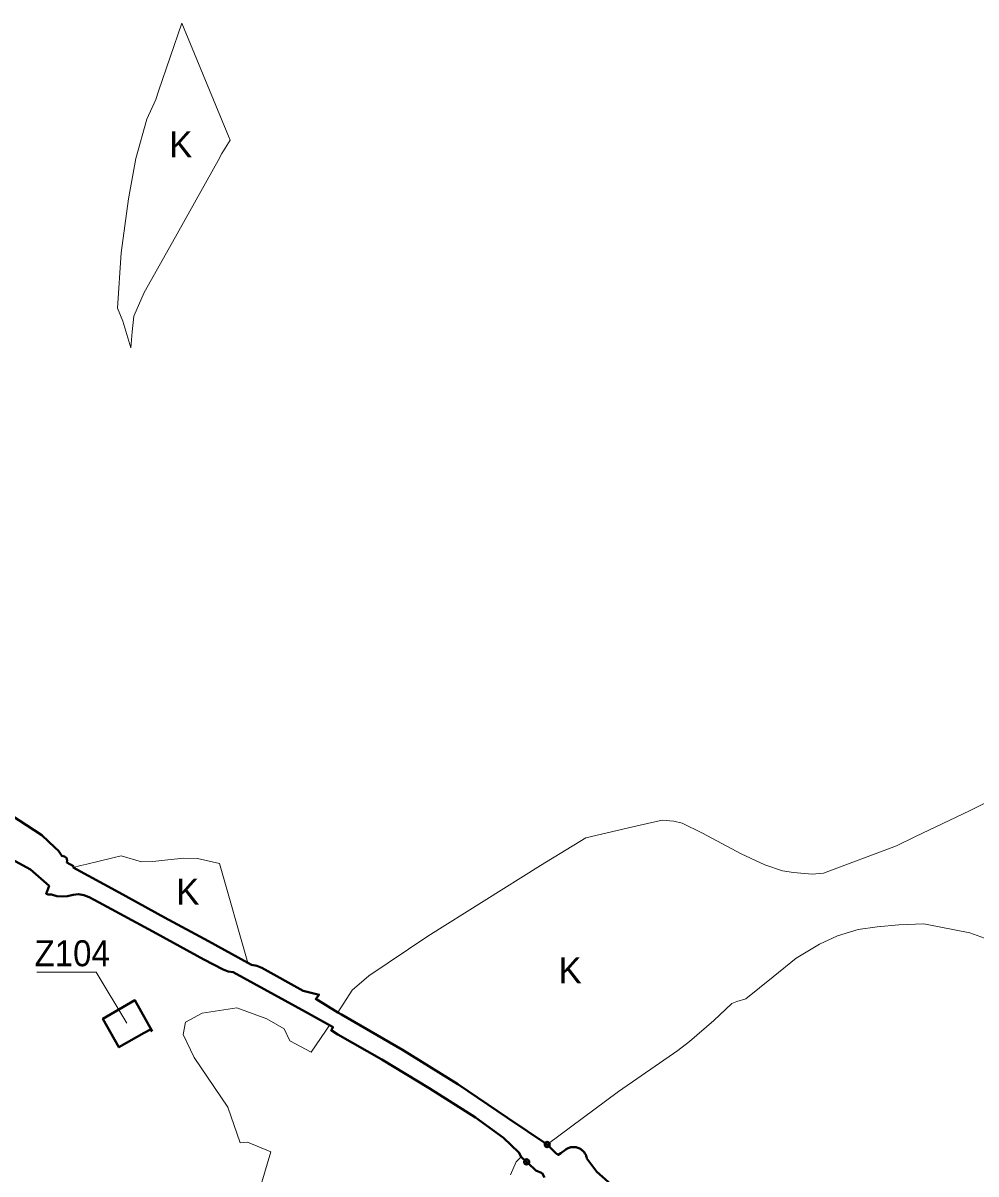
# Model space of a CAD drawing. Extents: x -650276 to -642489, y -1074311 to -1066658.
# Drawn here: x -646064 to -645184, y -1069193 to -1068130 of the extents above; entities that cross this region are included whole.
import ezdxf

# ---------------------------------------------------------------- set-up
doc = ezdxf.new("R2010")
doc.units = 0
doc.header["$LTSCALE"] = 9.6
doc.header["$PDMODE"] = 32
doc.header["$PDSIZE"] = 4.8
for name, color, linetype, lineweight in [('44', 7, 'Continuous', 40), ('45', 7, 'Continuous', 40), ('46', 7, 'Continuous', 13), ('47', 7, 'Continuous', 13), ('48', 7, 'Continuous', 13)]:
    doc.layers.add(name, color=color, linetype=linetype, lineweight=lineweight)

msp = doc.modelspace()

# ---------------------------------------------------------------- linework, layer by layer
at = {"layer": '44'}
for points in [[(-645579.94, -1069165.52), (-645616.63, -1069140.8), (-645662.44, -1069109.89), (-645713.61, -1069078.06), (-645770.04, -1069045.34), (-645773.38, -1069043.46), (-645793.638, -1069031.021), (-645790.53, -1069027.19), (-645805.16, -1069023.52), (-645843.56, -1069002.41), (-645848.18, -1069000.48), (-645852.91, -1068999.62), (-645856.26, -1068997.79), (-645892.77, -1068977.86), (-645933.28, -1068955.74), (-645975.31, -1068932.8), (-646017.55, -1068909.75), (-646017.39, -1068908.42), (-646023.56, -1068905.05), (-646023.13, -1068903.12), (-646023.92, -1068900.73), (-646025.57, -1068899.39), (-646028.18, -1068898.89), (-646031.31, -1068894.32), (-646034.65, -1068891.12), (-646046.48, -1068879.92), (-646074.78, -1068861.51)], [(-646074.51, -1068901.9), (-646057.13, -1068911.62), (-646039.84, -1068926.67), (-646042.5, -1068933.91), (-646040.65, -1068934.59), (-646037.5, -1068934.7), (-646032.61, -1068936.1)], [(-646032.61, -1068936.1), (-646027.69, -1068936.6), (-646022.77, -1068936.12), (-646017.6, -1068934.89), (-646012.64, -1068934.34), (-646007.7, -1068935.18), (-646002.95, -1068936.95), (-645993.5, -1068942.1), (-645940.77, -1068970.74), (-645896.91, -1068994.75), (-645879.17, -1069004.02), (-645874.49, -1069005.73), (-645869.83, -1069006.45), (-645850.79, -1069016.84), (-645803.29, -1069042.92), (-645781.12, -1069055.29), (-645777.73, -1069057.2), (-645779.49, -1069059.92), (-645773.29, -1069063.99), (-645732.65, -1069086.82), (-645688.87, -1069113.44), (-645646.08, -1069140.37), (-645620.2, -1069159.26), (-645606.11, -1069172.98), (-645603.91, -1069176.86), (-645599, -1069181.48)], [(-645571.9, -1069173.43), (-645579.94, -1069165.52), (-645579.94, -1069165.52)], [(-645543.43, -1069178.39), (-645543.547, -1069177.727), (-645543.706, -1069177.053), (-645543.907, -1069176.37), (-645544.154, -1069175.682), (-645544.448, -1069174.993), (-645544.792, -1069174.308), (-645545.186, -1069173.63), (-645545.631, -1069172.966), (-645546.127, -1069172.32), (-645546.674, -1069171.699), (-645547.269, -1069171.107), (-645547.91, -1069170.551), (-645548.594, -1069170.034), (-645549.317, -1069169.563), (-645550.076, -1069169.141), (-645550.863, -1069168.772), (-645551.674, -1069168.459), (-645552.504, -1069168.203), (-645553.344, -1069168.007), (-645554.191, -1069167.87), (-645555.036, -1069167.793), (-645555.875, -1069167.772), (-645556.702, -1069167.808), (-645557.511, -1069167.896), (-645558.298, -1069168.035), (-645559.06, -1069168.219), (-645559.793, -1069168.445), (-645560.494, -1069168.709), (-645561.162, -1069169.007), (-645561.794, -1069169.334), (-645562.39, -1069169.686), (-645562.95, -1069170.06), (-645567.5, -1069173.46), (-645569.81, -1069175.03), (-645571.9, -1069173.43)], [(-645599, -1069181.48), (-645599, -1069181.48), (-645592.24, -1069187.73), (-645590.41, -1069189.45), (-645584.73, -1069191.88), (-645582.63, -1069195.88)], [(-645166.67, -1069629), (-645184.88, -1069596.58), (-645202.56, -1069568.23), (-645230.1, -1069525.98), (-645253.4, -1069493.06), (-645278.31, -1069461.33), (-645281.4, -1069458.4), (-645290.5, -1069449.03), (-645299.61, -1069437.97), (-645306.16, -1069425.55), (-645314.14, -1069412.54), (-645321.1, -1069405.21), (-645326.59, -1069396.64), (-645350.63, -1069363.98), (-645371.12, -1069339.47), (-645376.38, -1069332.65), (-645400.07, -1069313.32), (-645424.8, -1069295.24), (-645458.45, -1069265.56), (-645494.13, -1069227.63), (-645515.89, -1069206.66), (-645534.25, -1069190.56), (-645543.43, -1069178.39)]]:
    msp.add_lwpolyline(points, dxfattribs=at)
for p in [(-645579.94, -1069165.52), (-645599, -1069181.48)]:
    msp.add_point(p, dxfattribs=at)
at = {"layer": '45'}
for points in [[(-645944.69, -1069060.7), (-645960.67, -1069032.26), (-645990.13, -1069049.3), (-645975.48, -1069075.71), (-645952.21, -1069062.4)], [(-645944.69, -1069060.7), (-645960.67, -1069032.26), (-645990.13, -1069049.3), (-645975.48, -1069075.71), (-645952.21, -1069062.4)], [(-645952.21, -1069062.4), (-645946.84, -1069059.58), (-645944.69, -1069060.7)], [(-645952.21, -1069062.4), (-645946.84, -1069059.58), (-645944.69, -1069060.7)]]:
    msp.add_lwpolyline(points, dxfattribs=at)
at = {"layer": '46'}
msp.add_lwpolyline([(-646051.21, -1069006.26), (-645996.286, -1069006.26), (-645968.211, -1069053.466)], dxfattribs=at)
msp.add_lwpolyline([(-646051.21, -1069006.26), (-645996.286, -1069006.26), (-645968.211, -1069053.466)], dxfattribs=at)
at = {"layer": '47'}
msp.add_lwpolyline([(-645874.15, -1068234.44), (-645917.44, -1068129.99), (-645938.87, -1068193.06), (-645941.41, -1068200.54), (-645949.52, -1068218.72), (-645959.76, -1068255.23), (-645966.56, -1068292.38), (-645973.25, -1068342.08), (-645976.63, -1068393.14), (-645971.94, -1068405.38), (-645964.53, -1068429.83), (-645963.12, -1068415.21), (-645961.7, -1068400.54), (-645952.21, -1068378.95), (-645926.06, -1068332.18), (-645883.87, -1068256.88), (-645880.28, -1068250.47), (-645872.64, -1068238.08)], close=True, dxfattribs=at)
for points in [[(-645239.85, -1068880.94), (-645190.22, -1068857.23), (-645124.36, -1068824.11)], [(-645544.33, -1068882.17), (-645500.83, -1068872.25), (-645473.89, -1068866.13), (-645462.97, -1068866.88), (-645455.34, -1068868.9), (-645436.72, -1068877.85), (-645400.92, -1068897.18), (-645379.06, -1068907.27), (-645362.84, -1068912.83), (-645352.46, -1068914.25), (-645335.45, -1068915.77)], [(-645426.3, -1069051.02), (-645448.49, -1069070.45), (-645459.5, -1069078.59), (-645514.08, -1069116.5), (-645579.94, -1069165.52), (-645616.63, -1069140.8), (-645662.44, -1069109.89), (-645694.447, -1069089.98), (-645713.61, -1069078.06), (-645770.04, -1069045.34), (-645773.38, -1069043.46), (-645760.07, -1069023.11), (-645744.65, -1069009.71), (-645690.34, -1068973.16), (-645586.28, -1068907.71), (-645544.33, -1068882.17)], [(-645335.45, -1068915.77), (-645324.79, -1068914.82), (-645257.5, -1068889.68), (-645239.85, -1068880.94)], [(-645973.36, -1068898.93), (-645980.93, -1068900.85), (-645994.9, -1068904.1), (-646004.88, -1068906.5), (-646010.48, -1068907.86), (-646017.55, -1068909.75), (-645975.31, -1068932.8), (-645933.28, -1068955.74)], [(-645882.63, -1068905.88), (-645902.91, -1068901.43), (-645915.61, -1068901.02), (-645930.1, -1068902.47), (-645944.23, -1068904.13), (-645954.59, -1068904.41), (-645973.36, -1068898.93)], [(-645933.28, -1068955.74), (-645892.77, -1068977.86), (-645856.26, -1068997.79), (-645882.63, -1068905.88)], [(-645131.73, -1068995.69), (-645159.37, -1068981.11), (-645189.84, -1068969.91), (-645229.27, -1068962.28), (-645232.4, -1068961.67), (-645255.21, -1068962.49), (-645275.45, -1068964.38), (-645292.77, -1068966.91), (-645311.99, -1068972.74), (-645328.55, -1068980.37), (-645350.17, -1068993.33), (-645371.35, -1069010.64), (-645396.53, -1069030.88)], [(-645396.53, -1069030.88), (-645405.02, -1069033.34), (-645409.61, -1069035.17), (-645426.3, -1069051.02)], [(-645797.957, -1069080.052), (-645817.59, -1069069.6), (-645822.85, -1069058.8), (-645838.99, -1069049.31), (-645866.69, -1069039.37), (-645898.57, -1069044.24), (-645913.8, -1069052.51), (-645916.2, -1069063.8), (-645905.94, -1069085.11), (-645874.98, -1069131.01), (-645863.38, -1069163.79), (-645856.76, -1069163.17), (-645835.157, -1069172.184)], [(-645613.9, -1069193.45), (-645608.71, -1069181.51), (-645603.91, -1069176.86), (-645606.11, -1069172.98), (-645620.2, -1069159.26), (-645646.08, -1069140.37), (-645688.87, -1069113.44), (-645732.65, -1069086.82), (-645773.29, -1069063.99), (-645779.49, -1069059.92), (-645777.73, -1069057.2), (-645781.12, -1069055.29), (-645784.69, -1069060.74), (-645797.957, -1069080.052)], [(-645835.157, -1069172.184), (-645859.43, -1069254.08), (-645864.96, -1069269.78), (-645867.42, -1069274.21), (-645866.45, -1069276.32), (-645877.15, -1069319.06), (-645877.15, -1069319.06), (-645889.29, -1069330.52), (-645921.56, -1069346.6), (-645935.33, -1069340.64), (-645938.89, -1069341.56), (-645938.399, -1069347.452)]]:
    msp.add_lwpolyline(points, dxfattribs=at)

# ---------------------------------------------------------------- texts
at = {"layer": '46', "width": 0.95}
msp.add_text('Z104', height=24, dxfattribs=at).set_placement((-646053.286, -1069000.877))
msp.add_text('Z104', height=24, dxfattribs=at).set_placement((-646053.286, -1069000.877))
at = {"layer": '48'}
for p in [(-645928.983, -1068254.123), (-645928.983, -1068254.123), (-645922.543, -1068943.866), (-645922.543, -1068943.866), (-645569.606, -1069016.557), (-645569.606, -1069016.557)]:
    msp.add_text('K', height=24, dxfattribs=at).set_placement(p)

doc.saveas('drawing.dxf')
